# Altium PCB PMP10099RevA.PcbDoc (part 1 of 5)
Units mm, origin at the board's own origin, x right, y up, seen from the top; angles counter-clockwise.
Board outline 227.58 x 89.92 mm, 2 copper layers (Top Layer, Bottom Layer), stack 1.575 mm thick; 558 components, 261 nets, 1374 pads, 560 vias.
Unrouted connection lines stored in the file: 7.
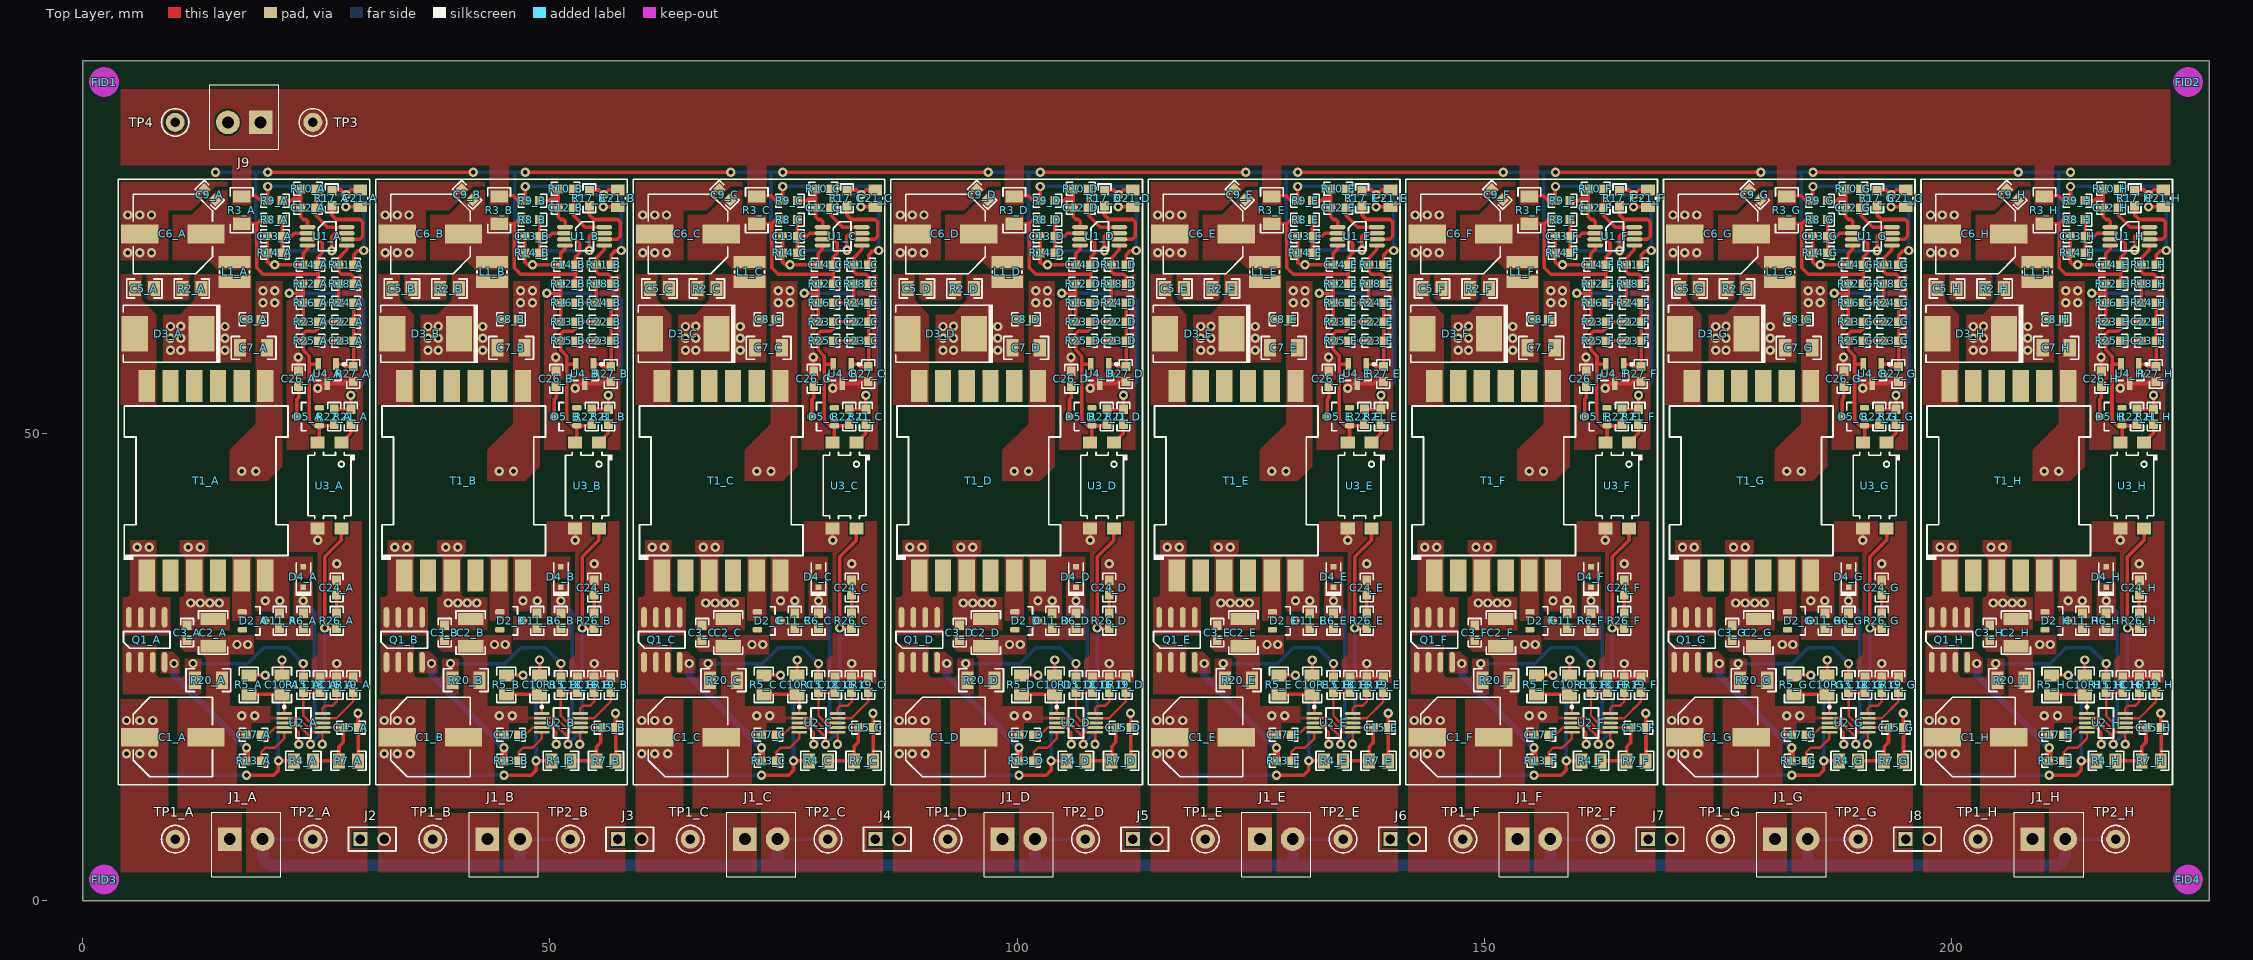
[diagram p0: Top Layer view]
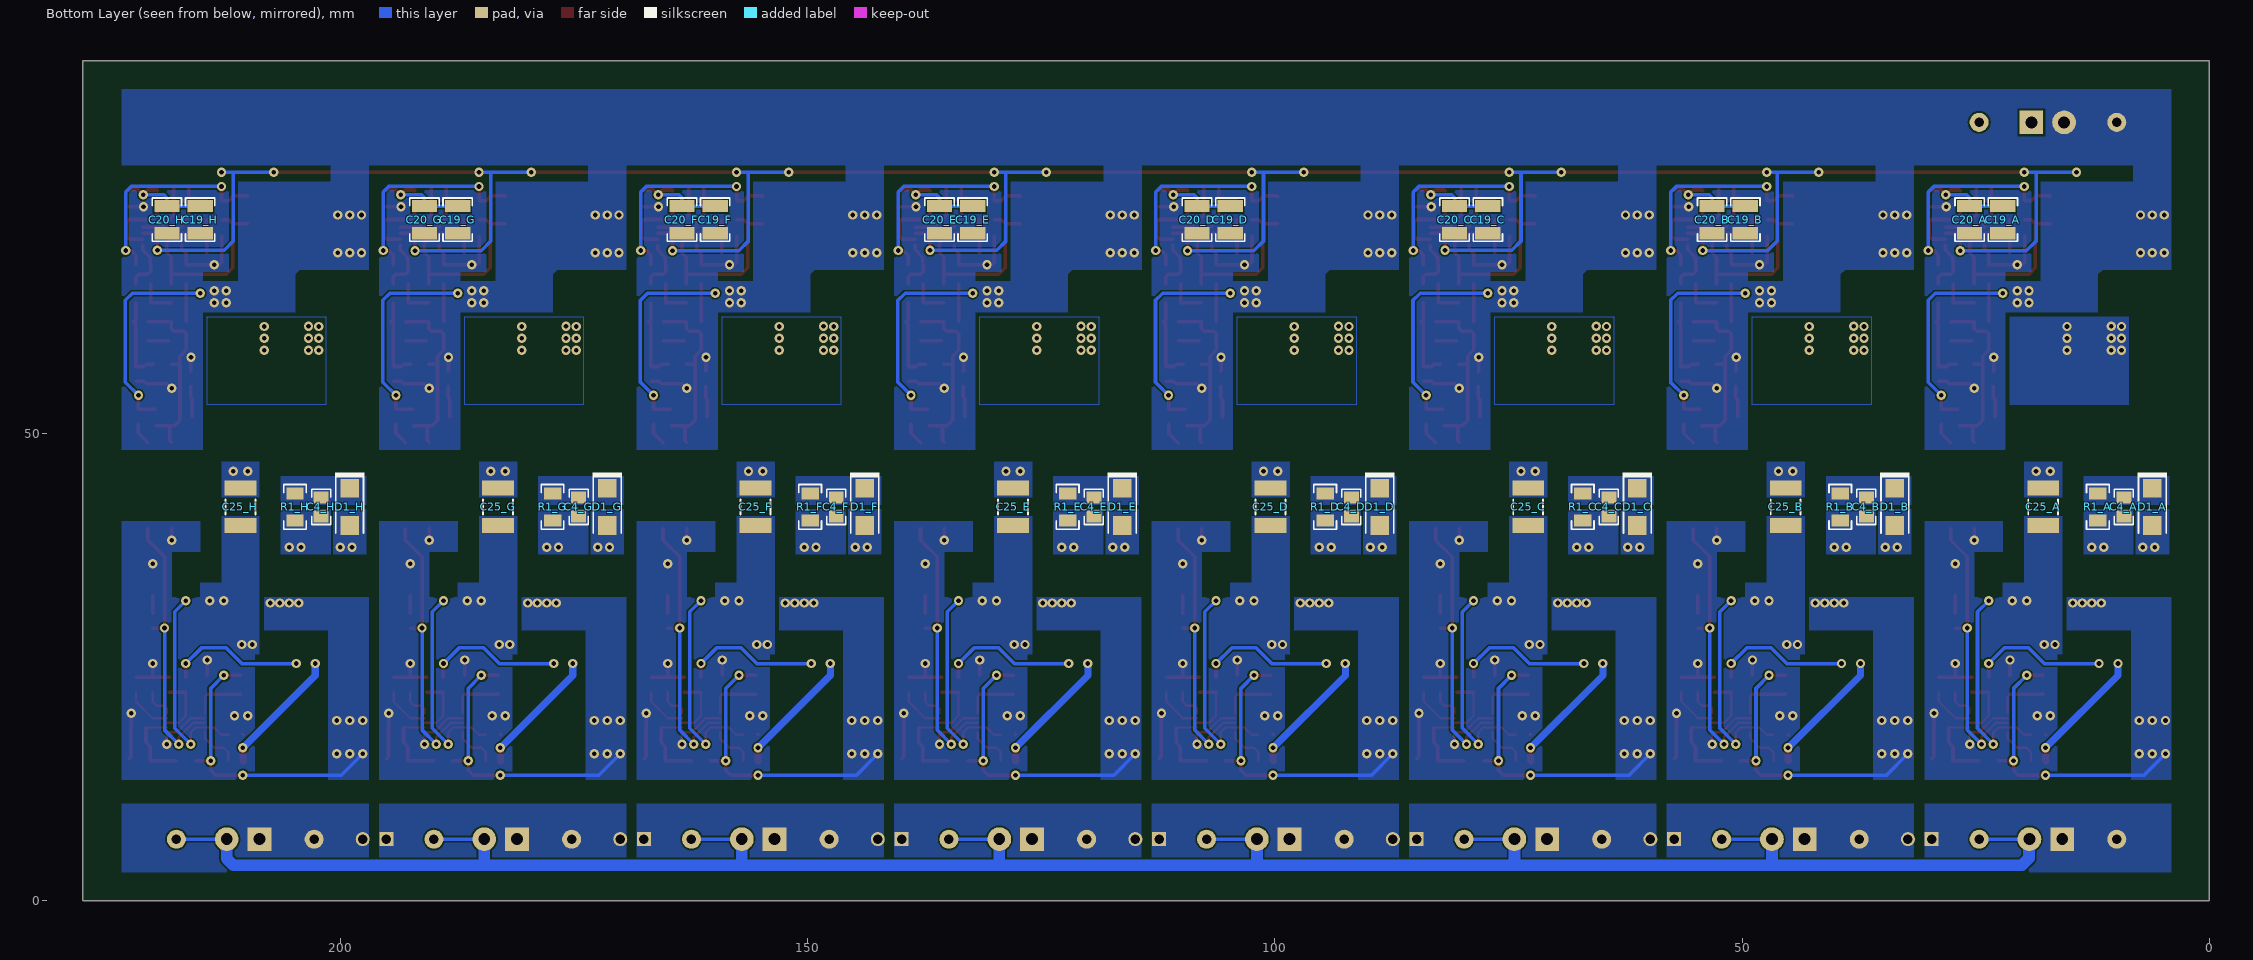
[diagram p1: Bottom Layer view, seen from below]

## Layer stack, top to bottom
Top Layer: signal copper 0.0356
Dielectric: core 1.5037, FR-4, Dk 4.8
Bottom Layer: signal copper 0.0356

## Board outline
0,0 227.584,0 227.584,89.916 0,89.916

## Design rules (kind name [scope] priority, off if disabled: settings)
Clearance [All] p1: gap=0.2
DiffPairsRouting [All] p1: maxlimit=10 minlimit=0.125 mostfreqgap=0.15 maxuncoupledlength=12.7
FabricationTestPointUsage FabricationTestPointUsage_1 [All] p1: valid=0 allowmultiple=FALSE
FabricationTestpoint FabricationTestpoint_1 [All] p1: side=3 testpointundercomponent=TRUE minsize=1.016 maxsize=2.54 preferedsize=1.524 minholesize=0 maxholesize=1.016 preferedholesize=0.813 testpointgrid=0.025 allowsidetop=TRUE allowsidebottom=TRUE usegrid=TRUE gridtolerance=0
Height [All] p1: minheight=0 maxheight=25.42 prefheight=12.7
HoleSize [All] p1: absolutevalues=TRUE maxlimit=6 minlimit=0.3 maxpercent=80.000 minpercent=20.000
HoleSize FabricationTestpoint [All] p2 off: absolutevalues=TRUE maxlimit=2.54 minlimit=0.025 maxpercent=80.000 minpercent=20.000
HoleSize FabricationTestPointUsage [All] p3 off: absolutevalues=TRUE maxlimit=2.54 minlimit=0.025 maxpercent=80.000 minpercent=20.000
MinimumAnnularRing [All] p1: minimumring=0.15
MinimumSolderMaskSliver [All] p1: minsoldermaskwidth=0.025
PlaneClearance [All] p1: clearance=0.5
PlaneConnect [All] p1: planeconnectstyle=Direct reliefexpansion=0.4 reliefentries=4 reliefconductorwidth=0.15 reliefairgap=0.15
PolygonConnect [All] p1: connectstyle=Direct reliefconductorwidth=0.15 reliefentries=4 polygonreliefangle="90 Angle" airgapwidth=0.254
RoomDefinition "PMP10099RevA - Top Level" [InComponentClass('PMP10099RevA - Top Level')] p1: confinementstyle=ConfineIn formatcopy=TRUE lockcomponents=FALSE outline 0,0 0,89.916 227.584,89.916 227.584,0
RoomDefinition H [InComponentClass('H')] p2: confinementstyle=ConfineIn formatcopy=TRUE lockcomponents=FALSE outline 196.723,2.54 223.647,2.54 223.647,77.216 196.723,77.216
RoomDefinition G [InComponentClass('G')] p3: confinementstyle=ConfineIn formatcopy=TRUE lockcomponents=FALSE outline 169.164,77.216 195.836,77.216 195.836,2.794 196.088,2.54 169.164,2.54
RoomDefinition F [InComponentClass('F')] p4: confinementstyle=ConfineIn formatcopy=TRUE lockcomponents=FALSE outline 141.605,2.54 168.529,2.54 168.529,77.216 141.605,77.216
RoomDefinition E [InComponentClass('E')] p5: confinementstyle=ConfineIn formatcopy=TRUE lockcomponents=FALSE outline 114.046,77.216 140.97,77.216 140.97,2.54 114.046,2.54
RoomDefinition D [InComponentClass('D')] p6: confinementstyle=ConfineIn formatcopy=TRUE lockcomponents=FALSE outline 86.487,2.54 113.411,2.54 113.411,77.216 86.487,77.216
RoomDefinition C [InComponentClass('C')] p7: confinementstyle=ConfineIn formatcopy=TRUE lockcomponents=FALSE outline 58.928,2.54 85.852,2.54 85.852,77.216 58.928,77.216
RoomDefinition B [InComponentClass('B')] p8: confinementstyle=ConfineIn formatcopy=TRUE lockcomponents=FALSE outline 31.369,2.54 31.369,77.216 58.293,77.216 58.293,2.54
RoomDefinition A [InComponentClass('A')] p9: confinementstyle=ConfineIn formatcopy=TRUE lockcomponents=FALSE outline 3.81,2.54 3.81,77.216 30.734,77.216 30.734,2.54
RoutingCorners [All] p1: cornerstyle=45-Degree minsetback=1.25 maxsetback=1.25
RoutingVias [All] p1: holewidth=0.3 width=0.7 viastyle="Through Hole" minholewidth=0.3 minwidth=0.5 maxholewidth=1 maxwidth=1.5
SilkToSilkClearance [All] p1: silktosilkclearance=0.1
SilkscreenOverComponentPads [All] p1: minsilkscreentomaskgap=0.127
SolderMaskExpansion [All] p1: expansion=0.075
Width [All] p1: maxlimit=10 minlimit=0.15 preferedwidth=0.254 minimp=50.000000 maximp=50.000000 favimp=50.000000
17 further rules are at their usual default settings.

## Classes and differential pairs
component class "PMP10099RevA - Top Level": FID1 FID2 FID3 FID4 J2 J3 J4 J5 J6 J7 J8 J9 TP3 TP4
component class A: C1_A C2_A C3_A C4_A C5_A C6_A C7_A C8_A C9_A C10_A C11_A C12_A C13_A C14_A C15_A C16_A C17_A C18_A C19_A C20_A C21_A C22_A C23_A C24_A C25_A C26_A D1_A D2_A D3_A D4_A D5_A J1_A L1_A Q1_A R1_A R2_A R3_A R4_A R5_A R6_A R7_A R8_A R9_A R10_A R11_A R12_A R13_A R14_A R15_A R16_A R17_A R18_A R19_A R20_A R21_A R22_A R23_A R24_A R25_A R26_A R27_A T1_A TP1_A TP2_A U1_A U2_A U3_A U4_A
component class Header: J2 J3 J4 J5 J6 J7 J8
component class B: C1_B C2_B C3_B C4_B C5_B C6_B C7_B C8_B C9_B C10_B C11_B C12_B C13_B C14_B C15_B C16_B C17_B C18_B C19_B C20_B C21_B C22_B C23_B C24_B C25_B C26_B D1_B D2_B D3_B D4_B D5_B J1_B L1_B Q1_B R1_B R2_B R3_B R4_B R5_B R6_B R7_B R8_B R9_B R10_B R11_B R12_B R13_B R14_B R15_B R16_B R17_B R18_B R19_B R20_B R21_B R22_B R23_B R24_B R25_B R26_B R27_B T1_B TP1_B TP2_B U1_B U2_B U3_B U4_B
component class C: C1_C C2_C C3_C C4_C C5_C C6_C C7_C C8_C C9_C C10_C C11_C C12_C C13_C C14_C C15_C C16_C C17_C C18_C C19_C C20_C C21_C C22_C C23_C C24_C C25_C C26_C D1_C D2_C D3_C D4_C D5_C J1_C L1_C Q1_C R1_C R2_C R3_C R4_C R5_C R6_C R7_C R8_C R9_C R10_C R11_C R12_C R13_C R14_C R15_C R16_C R17_C R18_C R19_C R20_C R21_C R22_C R23_C R24_C R25_C R26_C R27_C T1_C TP1_C TP2_C U1_C U2_C U3_C U4_C
component class D: C1_D C2_D C3_D C4_D C5_D C6_D C7_D C8_D C9_D C10_D C11_D C12_D C13_D C14_D C15_D C16_D C17_D C18_D C19_D C20_D C21_D C22_D C23_D C24_D C25_D C26_D D1_D D2_D D3_D D4_D D5_D J1_D L1_D Q1_D R1_D R2_D R3_D R4_D R5_D R6_D R7_D R8_D R9_D R10_D R11_D R12_D R13_D R14_D R15_D R16_D R17_D R18_D R19_D R20_D R21_D R22_D R23_D R24_D R25_D R26_D R27_D T1_D TP1_D TP2_D U1_D U2_D U3_D U4_D
component class E: C1_E C2_E C3_E C4_E C5_E C6_E C7_E C8_E C9_E C10_E C11_E C12_E C13_E C14_E C15_E C16_E C17_E C18_E C19_E C20_E C21_E C22_E C23_E C24_E C25_E C26_E D1_E D2_E D3_E D4_E D5_E J1_E L1_E Q1_E R1_E R2_E R3_E R4_E R5_E R6_E R7_E R8_E R9_E R10_E R11_E R12_E R13_E R14_E R15_E R16_E R17_E R18_E R19_E R20_E R21_E R22_E R23_E R24_E R25_E R26_E R27_E T1_E TP1_E TP2_E U1_E U2_E U3_E U4_E
component class F: C1_F C2_F C3_F C4_F C5_F C6_F C7_F C8_F C9_F C10_F C11_F C12_F C13_F C14_F C15_F C16_F C17_F C18_F C19_F C20_F C21_F C22_F C23_F C24_F C25_F C26_F D1_F D2_F D3_F D4_F D5_F J1_F L1_F Q1_F R1_F R2_F R3_F R4_F R5_F R6_F R7_F R8_F R9_F R10_F R11_F R12_F R13_F R14_F R15_F R16_F R17_F R18_F R19_F R20_F R21_F R22_F R23_F R24_F R25_F R26_F R27_F T1_F TP1_F TP2_F U1_F U2_F U3_F U4_F
component class G: C1_G C2_G C3_G C4_G C5_G C6_G C7_G C8_G C9_G C10_G C11_G C12_G C13_G C14_G C15_G C16_G C17_G C18_G C19_G C20_G C21_G C22_G C23_G C24_G C25_G C26_G D1_G D2_G D3_G D4_G D5_G J1_G L1_G Q1_G R1_G R2_G R3_G R4_G R5_G R6_G R7_G R8_G R9_G R10_G R11_G R12_G R13_G R14_G R15_G R16_G R17_G R18_G R19_G R20_G R21_G R22_G R23_G R24_G R25_G R26_G R27_G T1_G TP1_G TP2_G U1_G U2_G U3_G U4_G
component class H: C1_H C2_H C3_H C4_H C5_H C6_H C7_H C8_H C9_H C10_H C11_H C12_H C13_H C14_H C15_H C16_H C17_H C18_H C19_H C20_H C21_H C22_H C23_H C24_H C25_H C26_H D1_H D2_H D3_H D4_H D5_H J1_H L1_H Q1_H R1_H R2_H R3_H R4_H R5_H R6_H R7_H R8_H R9_H R10_H R11_H R12_H R13_H R14_H R15_H R16_H R17_H R18_H R19_H R20_H R21_H R22_H R23_H R24_H R25_H R26_H R27_H T1_H TP1_H TP2_H U1_H U2_H U3_H U4_H
channel class "PMP10099RevA - Circuit": A B C D E F G H
component class FiducialMark: FID1 FID2 FID3 FID4

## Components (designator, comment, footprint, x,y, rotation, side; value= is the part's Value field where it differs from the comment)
C1_A "EEE-FK1K220P" SM_RADIAL_F 9.652,17.526 r0 top (schematic designator C1)
C1_B "EEE-FK1K220P" SM_RADIAL_F 37.211,17.526 r0 top (schematic designator C1)
C1_C "EEE-FK1K220P" SM_RADIAL_F 64.77,17.526 r0 top (schematic designator C1)
C1_D "EEE-FK1K220P" SM_RADIAL_F 92.329,17.526 r0 top (schematic designator C1)
C1_E "EEE-FK1K220P" SM_RADIAL_F 119.888,17.526 r0 top (schematic designator C1)
C1_F "EEE-FK1K220P" SM_RADIAL_F 147.447,17.526 r0 top (schematic designator C1)
C1_G "EEE-FK1K220P" SM_RADIAL_F 175.006,17.526 r0 top (schematic designator C1)
C1_H "EEE-FK1K220P" SM_RADIAL_F 202.565,17.526 r0 top (schematic designator C1)
C2_A "GRM32ER72A225KA35L" 1210 13.97,28.702 r270 top (schematic designator C2)
C2_B "GRM32ER72A225KA35L" 1210 41.529,28.702 r270 top (schematic designator C2)
C2_C "GRM32ER72A225KA35L" 1210 69.088,28.702 r270 top (schematic designator C2)
C2_D "GRM32ER72A225KA35L" 1210 96.647,28.702 r270 top (schematic designator C2)
C2_E "GRM32ER72A225KA35L" 1210 124.206,28.702 r270 top (schematic designator C2)
C2_F "GRM32ER72A225KA35L" 1210 151.765,28.702 r270 top (schematic designator C2)
C2_G "GRM32ER72A225KA35L" 1210 179.324,28.702 r270 top (schematic designator C2)
C2_H "GRM32ER72A225KA35L" 1210 206.883,28.702 r270 top (schematic designator C2)
C3_A "GCM188R71H104KA57D" 0603 11.176,28.702 r270 top (schematic designator C3)
C3_B "GCM188R71H104KA57D" 0603 38.735,28.702 r270 top (schematic designator C3)
C3_C "GCM188R71H104KA57D" 0603 66.294,28.702 r270 top (schematic designator C3)
C3_D "GCM188R71H104KA57D" 0603 93.853,28.702 r270 top (schematic designator C3)
C3_E "GCM188R71H104KA57D" 0603 121.412,28.702 r270 top (schematic designator C3)
C3_F "GCM188R71H104KA57D" 0603 148.971,28.702 r270 top (schematic designator C3)
C3_G "GCM188R71H104KA57D" 0603 176.53,28.702 r270 top (schematic designator C3)
C3_H "GCM188R71H104KA57D" 0603 204.089,28.702 r270 top (schematic designator C3)
C4_A "HMK212B7104KG-T" 0805_HV 9.144,42.164 r90 bottom (schematic designator C4)
C4_B "HMK212B7104KG-T" 0805_HV 36.703,42.164 r90 bottom (schematic designator C4)
C4_C "HMK212B7104KG-T" 0805_HV 64.262,42.164 r90 bottom (schematic designator C4)
C4_D "HMK212B7104KG-T" 0805_HV 91.821,42.164 r90 bottom (schematic designator C4)
C4_E "HMK212B7104KG-T" 0805_HV 119.38,42.164 r90 bottom (schematic designator C4)
C4_F "HMK212B7104KG-T" 0805_HV 146.939,42.164 r90 bottom (schematic designator C4)
C4_G "HMK212B7104KG-T" 0805_HV 174.498,42.164 r90 bottom (schematic designator C4)
C4_H "HMK212B7104KG-T" 0805_HV 202.057,42.164 r90 bottom (schematic designator C4)
C5_A "GRM2195C2A330JZ01D" 0805_HV 6.604,65.532 r180 top (schematic designator C5)
C5_B "GRM2195C2A330JZ01D" 0805_HV 34.163,65.532 r180 top (schematic designator C5)
C5_C "GRM2195C2A330JZ01D" 0805_HV 61.722,65.532 r180 top (schematic designator C5)
C5_D "GRM2195C2A330JZ01D" 0805_HV 89.281,65.532 r180 top (schematic designator C5)
C5_E "GRM2195C2A330JZ01D" 0805_HV 116.84,65.532 r180 top (schematic designator C5)
C5_F "GRM2195C2A330JZ01D" 0805_HV 144.399,65.532 r180 top (schematic designator C5)
C5_G "GRM2195C2A330JZ01D" 0805_HV 171.958,65.532 r180 top (schematic designator C5)
C5_H "GRM2195C2A330JZ01D" 0805_HV 199.517,65.532 r180 top (schematic designator C5)
C6_A "EEE-FK1C331P" SM_RADIAL_F 9.652,71.374 r180 top (schematic designator C6)
C6_B "EEE-FK1C331P" SM_RADIAL_F 37.211,71.374 r180 top (schematic designator C6)
C6_C "EEE-FK1C331P" SM_RADIAL_F 64.77,71.374 r180 top (schematic designator C6)
C6_D "EEE-FK1C331P" SM_RADIAL_F 92.329,71.374 r180 top (schematic designator C6)
C6_E "EEE-FK1C331P" SM_RADIAL_F 119.888,71.374 r180 top (schematic designator C6)
C6_F "EEE-FK1C331P" SM_RADIAL_F 147.447,71.374 r180 top (schematic designator C6)
C6_G "EEE-FK1C331P" SM_RADIAL_F 175.006,71.374 r180 top (schematic designator C6)
C6_H "EEE-FK1C331P" SM_RADIAL_F 202.565,71.374 r180 top (schematic designator C6)
C7_A "GRM31CR71E106KA12L" 1206 18.288,59.182 r0 top (schematic designator C7)
C7_B "GRM31CR71E106KA12L" 1206 45.847,59.182 r0 top (schematic designator C7)
C7_C "GRM31CR71E106KA12L" 1206 73.406,59.182 r0 top (schematic designator C7)
C7_D "GRM31CR71E106KA12L" 1206 100.965,59.182 r0 top (schematic designator C7)
C7_E "GRM31CR71E106KA12L" 1206 128.524,59.182 r0 top (schematic designator C7)
C7_F "GRM31CR71E106KA12L" 1206 156.083,59.182 r0 top (schematic designator C7)
C7_G "GRM31CR71E106KA12L" 1206 183.642,59.182 r0 top (schematic designator C7)
C7_H "GRM31CR71E106KA12L" 1206 211.201,59.182 r0 top (schematic designator C7)
C8_A "GCM188R71H104KA57D" 0603 18.288,62.23 r0 top (schematic designator C8)
C8_B "GCM188R71H104KA57D" 0603 45.847,62.23 r0 top (schematic designator C8)
C8_C "GCM188R71H104KA57D" 0603 73.406,62.23 r0 top (schematic designator C8)
C8_D "GCM188R71H104KA57D" 0603 100.965,62.23 r0 top (schematic designator C8)
C8_E "GCM188R71H104KA57D" 0603 128.524,62.23 r0 top (schematic designator C8)
C8_F "GCM188R71H104KA57D" 0603 156.083,62.23 r0 top (schematic designator C8)
C8_G "GCM188R71H104KA57D" 0603 183.642,62.23 r0 top (schematic designator C8)
C8_H "GCM188R71H104KA57D" 0603 211.201,62.23 r0 top (schematic designator C8)
C9_A "GCM188R71H104KA57D" 0603 13.589,75.565 r135 top (schematic designator C9)
C9_B "GCM188R71H104KA57D" 0603 41.148,75.565 r135 top (schematic designator C9)
C9_C "GCM188R71H104KA57D" 0603 68.707,75.565 r135 top (schematic designator C9)
C9_D "GCM188R71H104KA57D" 0603 96.266,75.565 r135 top (schematic designator C9)
C9_E "GCM188R71H104KA57D" 0603 123.825,75.565 r135 top (schematic designator C9)
C9_F "GCM188R71H104KA57D" 0603 151.384,75.565 r135 top (schematic designator C9)
C9_G "GCM188R71H104KA57D" 0603 178.943,75.565 r135 top (schematic designator C9)
C9_H "GCM188R71H104KA57D" 0603 206.502,75.565 r135 top (schematic designator C9)
C10_A "HMK212B7104KG-T" 0805_HV 21.336,23.114 r90 top (schematic designator C10)
C10_B "HMK212B7104KG-T" 0805_HV 48.895,23.114 r90 top (schematic designator C10)
C10_C "HMK212B7104KG-T" 0805_HV 76.454,23.114 r90 top (schematic designator C10)
C10_D "HMK212B7104KG-T" 0805_HV 104.013,23.114 r90 top (schematic designator C10)
C10_E "HMK212B7104KG-T" 0805_HV 131.572,23.114 r90 top (schematic designator C10)
C10_F "HMK212B7104KG-T" 0805_HV 159.131,23.114 r90 top (schematic designator C10)
C10_G "HMK212B7104KG-T" 0805_HV 186.69,23.114 r90 top (schematic designator C10)
C10_H "HMK212B7104KG-T" 0805_HV 214.249,23.114 r90 top (schematic designator C10)
C11_A "GRM188R71E105KA12D" 0603 21.082,29.972 r90 top (schematic designator C11)
C11_B "GRM188R71E105KA12D" 0603 48.641,29.972 r90 top (schematic designator C11)
C11_C "GRM188R71E105KA12D" 0603 76.2,29.972 r90 top (schematic designator C11)
C11_D "GRM188R71E105KA12D" 0603 103.759,29.972 r90 top (schematic designator C11)
C11_E "GRM188R71E105KA12D" 0603 131.318,29.972 r90 top (schematic designator C11)
C11_F "GRM188R71E105KA12D" 0603 158.877,29.972 r90 top (schematic designator C11)
C11_G "GRM188R71E105KA12D" 0603 186.436,29.972 r90 top (schematic designator C11)
C11_H "GRM188R71E105KA12D" 0603 213.995,29.972 r90 top (schematic designator C11)
C12_A "GRM1885C1H560JA01D" 0603 24.13,74.168 r180 top (schematic designator C12)
C12_B "GRM1885C1H560JA01D" 0603 51.689,74.168 r180 top (schematic designator C12)
C12_C "GRM1885C1H560JA01D" 0603 79.248,74.168 r180 top (schematic designator C12)
C12_D "GRM1885C1H560JA01D" 0603 106.807,74.168 r180 top (schematic designator C12)
C12_E "GRM1885C1H560JA01D" 0603 134.366,74.168 r180 top (schematic designator C12)
C12_F "GRM1885C1H560JA01D" 0603 161.925,74.168 r180 top (schematic designator C12)
C12_G "GRM1885C1H560JA01D" 0603 189.484,74.168 r180 top (schematic designator C12)
C12_H "GRM1885C1H560JA01D" 0603 217.043,74.168 r180 top (schematic designator C12)
C13_A "GRM1885C1H560JA01D" 0603 20.574,71.12 r180 top (schematic designator C13)
C13_B "GRM1885C1H560JA01D" 0603 48.133,71.12 r180 top (schematic designator C13)
C13_C "GRM1885C1H560JA01D" 0603 75.692,71.12 r180 top (schematic designator C13)
C13_D "GRM1885C1H560JA01D" 0603 103.251,71.12 r180 top (schematic designator C13)
C13_E "GRM1885C1H560JA01D" 0603 130.81,71.12 r180 top (schematic designator C13)
C13_F "GRM1885C1H560JA01D" 0603 158.369,71.12 r180 top (schematic designator C13)
C13_G "GRM1885C1H560JA01D" 0603 185.928,71.12 r180 top (schematic designator C13)
C13_H "GRM1885C1H560JA01D" 0603 213.487,71.12 r180 top (schematic designator C13)
C14_A "GCM188R71H104KA57D" 0603 24.384,68.072 r180 top (schematic designator C14)
C14_B "GCM188R71H104KA57D" 0603 51.943,68.072 r180 top (schematic designator C14)
C14_C "GCM188R71H104KA57D" 0603 79.502,68.072 r180 top (schematic designator C14)
C14_D "GCM188R71H104KA57D" 0603 107.061,68.072 r180 top (schematic designator C14)
C14_E "GCM188R71H104KA57D" 0603 134.62,68.072 r180 top (schematic designator C14)
C14_F "GCM188R71H104KA57D" 0603 162.179,68.072 r180 top (schematic designator C14)
C14_G "GCM188R71H104KA57D" 0603 189.738,68.072 r180 top (schematic designator C14)
C14_H "GCM188R71H104KA57D" 0603 217.297,68.072 r180 top (schematic designator C14)
C15_A "GRM188R71H102KA01D" 0603 28.702,18.542 r0 top (schematic designator C15)
C15_B "GRM188R71H102KA01D" 0603 56.261,18.542 r0 top (schematic designator C15)
C15_C "GRM188R71H102KA01D" 0603 83.82,18.542 r0 top (schematic designator C15)
C15_D "GRM188R71H102KA01D" 0603 111.379,18.542 r0 top (schematic designator C15)
C15_E "GRM188R71H102KA01D" 0603 138.938,18.542 r0 top (schematic designator C15)
C15_F "GRM188R71H102KA01D" 0603 166.497,18.542 r0 top (schematic designator C15)
C15_G "GRM188R71H102KA01D" 0603 194.056,18.542 r0 top (schematic designator C15)
C15_H "GRM188R71H102KA01D" 0603 221.615,18.542 r0 top (schematic designator C15)
C16_A "GCM188R71H104KA57D" 0603 27.178,23.114 r90 top (schematic designator C16)
C16_B "GCM188R71H104KA57D" 0603 54.737,23.114 r90 top (schematic designator C16)
C16_C "GCM188R71H104KA57D" 0603 82.296,23.114 r90 top (schematic designator C16)
C16_D "GCM188R71H104KA57D" 0603 109.855,23.114 r90 top (schematic designator C16)
C16_E "GCM188R71H104KA57D" 0603 137.414,23.114 r90 top (schematic designator C16)
C16_F "GCM188R71H104KA57D" 0603 164.973,23.114 r90 top (schematic designator C16)
C16_G "GCM188R71H104KA57D" 0603 192.532,23.114 r90 top (schematic designator C16)
C16_H "GCM188R71H104KA57D" 0603 220.091,23.114 r90 top (schematic designator C16)
C17_A "GRM188R71E105KA12D" 0603 18.288,17.78 r180 top (schematic designator C17)
C17_B "GRM188R71E105KA12D" 0603 45.847,17.78 r180 top (schematic designator C17)
C17_C "GRM188R71E105KA12D" 0603 73.406,17.78 r180 top (schematic designator C17)
C17_D "GRM188R71E105KA12D" 0603 100.965,17.78 r180 top (schematic designator C17)
C17_E "GRM188R71E105KA12D" 0603 128.524,17.78 r180 top (schematic designator C17)
C17_F "GRM188R71E105KA12D" 0603 156.083,17.78 r180 top (schematic designator C17)
C17_G "GRM188R71E105KA12D" 0603 183.642,17.78 r180 top (schematic designator C17)
C17_H "GRM188R71E105KA12D" 0603 211.201,17.78 r180 top (schematic designator C17)
C18_A "GRM188R71H102KA01D" 0603 25.4,23.114 r90 top (schematic designator C18)
C18_B "GRM188R71H102KA01D" 0603 52.959,23.114 r90 top (schematic designator C18)
C18_C "GRM188R71H102KA01D" 0603 80.518,23.114 r90 top (schematic designator C18)
C18_D "GRM188R71H102KA01D" 0603 108.077,23.114 r90 top (schematic designator C18)
C18_E "GRM188R71H102KA01D" 0603 135.636,23.114 r90 top (schematic designator C18)
C18_F "GRM188R71H102KA01D" 0603 163.195,23.114 r90 top (schematic designator C18)
C18_G "GRM188R71H102KA01D" 0603 190.754,23.114 r90 top (schematic designator C18)
C18_H "GRM188R71H102KA01D" 0603 218.313,23.114 r90 top (schematic designator C18)
C19_A "GRM32ER70J476KE20L" 1210 22.098,72.898 r270 bottom (schematic designator C19)
C19_B "GRM32ER70J476KE20L" 1210 49.657,72.898 r270 bottom (schematic designator C19)
C19_C "GRM32ER70J476KE20L" 1210 77.216,72.898 r270 bottom (schematic designator C19)
C19_D "GRM32ER70J476KE20L" 1210 104.775,72.898 r270 bottom (schematic designator C19)
C19_E "GRM32ER70J476KE20L" 1210 132.334,72.898 r270 bottom (schematic designator C19)
C19_F "GRM32ER70J476KE20L" 1210 159.893,72.898 r270 bottom (schematic designator C19)
C19_G "GRM32ER70J476KE20L" 1210 187.452,72.898 r270 bottom (schematic designator C19)
C19_H "GRM32ER70J476KE20L" 1210 215.011,72.898 r270 bottom (schematic designator C19)
C20_A "GRM32ER70J476KE20L" 1210 25.654,72.898 r270 bottom (schematic designator C20)
C20_B "GRM32ER70J476KE20L" 1210 53.213,72.898 r270 bottom (schematic designator C20)
C20_C "GRM32ER70J476KE20L" 1210 80.772,72.898 r270 bottom (schematic designator C20)
C20_D "GRM32ER70J476KE20L" 1210 108.331,72.898 r270 bottom (schematic designator C20)
C20_E "GRM32ER70J476KE20L" 1210 135.89,72.898 r270 bottom (schematic designator C20)
C20_F "GRM32ER70J476KE20L" 1210 163.449,72.898 r270 bottom (schematic designator C20)
C20_G "GRM32ER70J476KE20L" 1210 191.008,72.898 r270 bottom (schematic designator C20)
C20_H "GRM32ER70J476KE20L" 1210 218.567,72.898 r270 bottom (schematic designator C20)
C21_A "GRM21BR71A106KE51K" 0805_140 29.718,75.184 r270 top (schematic designator C21)
C21_B "GRM21BR71A106KE51K" 0805_140 57.277,75.184 r270 top (schematic designator C21)
C21_C "GRM21BR71A106KE51K" 0805_140 84.836,75.184 r270 top (schematic designator C21)
C21_D "GRM21BR71A106KE51K" 0805_140 112.395,75.184 r270 top (schematic designator C21)
C21_E "GRM21BR71A106KE51K" 0805_140 139.954,75.184 r270 top (schematic designator C21)
C21_F "GRM21BR71A106KE51K" 0805_140 167.513,75.184 r270 top (schematic designator C21)
C21_G "GRM21BR71A106KE51K" 0805_140 195.072,75.184 r270 top (schematic designator C21)
C21_H "GRM21BR71A106KE51K" 0805_140 222.631,75.184 r270 top (schematic designator C21)
C22_A "GRM1885C1H220JA01D" 0603 28.194,61.976 r0 top (schematic designator C22)
C22_B "GRM1885C1H220JA01D" 0603 55.753,61.976 r0 top (schematic designator C22)
C22_C "GRM1885C1H220JA01D" 0603 83.312,61.976 r0 top (schematic designator C22)
C22_D "GRM1885C1H220JA01D" 0603 110.871,61.976 r0 top (schematic designator C22)
C22_E "GRM1885C1H220JA01D" 0603 138.43,61.976 r0 top (schematic designator C22)
C22_F "GRM1885C1H220JA01D" 0603 165.989,61.976 r0 top (schematic designator C22)
C22_G "GRM1885C1H220JA01D" 0603 193.548,61.976 r0 top (schematic designator C22)
C22_H "GRM1885C1H220JA01D" 0603 221.107,61.976 r0 top (schematic designator C22)
C23_A "GRM188R71H472KA01D" 0603 28.194,59.944 r0 top (schematic designator C23)
C23_B "GRM188R71H472KA01D" 0603 55.753,59.944 r0 top (schematic designator C23)
C23_C "GRM188R71H472KA01D" 0603 83.312,59.944 r0 top (schematic designator C23)
C23_D "GRM188R71H472KA01D" 0603 110.871,59.944 r0 top (schematic designator C23)
C23_E "GRM188R71H472KA01D" 0603 138.43,59.944 r0 top (schematic designator C23)
C23_F "GRM188R71H472KA01D" 0603 165.989,59.944 r0 top (schematic designator C23)
C23_G "GRM188R71H472KA01D" 0603 193.548,59.944 r0 top (schematic designator C23)
C23_H "GRM188R71H472KA01D" 0603 221.107,59.944 r0 top (schematic designator C23)
C24_A "GCM188R71H104KA57D" 0603 27.178,33.528 r90 top (schematic designator C24)
C24_B "GCM188R71H104KA57D" 0603 54.737,33.528 r90 top (schematic designator C24)
C24_C "GCM188R71H104KA57D" 0603 82.296,33.528 r90 top (schematic designator C24)
C24_D "GCM188R71H104KA57D" 0603 109.855,33.528 r90 top (schematic designator C24)
C24_E "GCM188R71H104KA57D" 0603 137.414,33.528 r90 top (schematic designator C24)
C24_F "GCM188R71H104KA57D" 0603 164.973,33.528 r90 top (schematic designator C24)
C24_G "GCM188R71H104KA57D" 0603 192.532,33.528 r90 top (schematic designator C24)
C24_H "GCM188R71H104KA57D" 0603 220.091,33.528 r90 top (schematic designator C24)
C25_A "1812GC102KA1" 1812 17.78,42.164 r270 bottom (schematic designator C25)
C25_B "1812GC102KA1" 1812 45.339,42.164 r270 bottom (schematic designator C25)
C25_C "1812GC102KA1" 1812 72.898,42.164 r270 bottom (schematic designator C25)
C25_D "1812GC102KA1" 1812 100.457,42.164 r270 bottom (schematic designator C25)
C25_E "1812GC102KA1" 1812 128.016,42.164 r270 bottom (schematic designator C25)
C25_F "1812GC102KA1" 1812 155.575,42.164 r270 bottom (schematic designator C25)
C25_G "1812GC102KA1" 1812 183.134,42.164 r270 bottom (schematic designator C25)
C25_H "1812GC102KA1" 1812 210.693,42.164 r270 bottom (schematic designator C25)
C26_A "GRM188R71E105KA12D" 0603 23.114,55.88 r90 top (schematic designator C26)
C26_B "GRM188R71E105KA12D" 0603 50.673,55.88 r90 top (schematic designator C26)
C26_C "GRM188R71E105KA12D" 0603 78.232,55.88 r90 top (schematic designator C26)
C26_D "GRM188R71E105KA12D" 0603 105.791,55.88 r90 top (schematic designator C26)
C26_E "GRM188R71E105KA12D" 0603 133.35,55.88 r90 top (schematic designator C26)
C26_F "GRM188R71E105KA12D" 0603 160.909,55.88 r90 top (schematic designator C26)
C26_G "GRM188R71E105KA12D" 0603 188.468,55.88 r90 top (schematic designator C26)
C26_H "GRM188R71E105KA12D" 0603 216.027,55.88 r90 top (schematic designator C26)
D1_A "MURA`10" SMA 6.096,42.164 r270 bottom (schematic designator D1)
D1_B "MURA`10" SMA 33.655,42.164 r270 bottom (schematic designator D1)
D1_C "MURA`10" SMA 61.214,42.164 r270 bottom (schematic designator D1)
D1_D "MURA`10" SMA 88.773,42.164 r270 bottom (schematic designator D1)
D1_E "MURA`10" SMA 116.332,42.164 r270 bottom (schematic designator D1)
D1_F "MURA`10" SMA 143.891,42.164 r270 bottom (schematic designator D1)
D1_G "MURA`10" SMA 171.45,42.164 r270 bottom (schematic designator D1)
D1_H "MURA`10" SMA 199.009,42.164 r270 bottom (schematic designator D1)
D2_A "BAS16" SOT-23 18.288,29.972 r0 top (schematic designator D2)
D2_B "BAS16" SOT-23 45.847,29.972 r0 top (schematic designator D2)
D2_C "BAS16" SOT-23 73.406,29.972 r0 top (schematic designator D2)
D2_D "BAS16" SOT-23 100.965,29.972 r0 top (schematic designator D2)
D2_E "BAS16" SOT-23 128.524,29.972 r0 top (schematic designator D2)
D2_F "BAS16" SOT-23 156.083,29.972 r0 top (schematic designator D2)
D2_G "BAS16" SOT-23 183.642,29.972 r0 top (schematic designator D2)
D2_H "BAS16" SOT-23 211.201,29.972 r0 top (schematic designator D2)
D3_A "MBRS360" SMC 9.144,60.706 r180 top (schematic designator D3)
D3_B "MBRS360" SMC 36.703,60.706 r180 top (schematic designator D3)
D3_C "MBRS360" SMC 64.262,60.706 r180 top (schematic designator D3)
D3_D "MBRS360" SMC 91.821,60.706 r180 top (schematic designator D3)
D3_E "MBRS360" SMC 119.38,60.706 r180 top (schematic designator D3)
D3_F "MBRS360" SMC 146.939,60.706 r180 top (schematic designator D3)
D3_G "MBRS360" SMC 174.498,60.706 r180 top (schematic designator D3)
D3_H "MBRS360" SMC 202.057,60.706 r180 top (schematic designator D3)
D4_A "BZX384-C12,115" sod-323 23.622,34.671 r90 top (schematic designator D4)
D4_B "BZX384-C12,115" sod-323 51.181,34.671 r90 top (schematic designator D4)
D4_C "BZX384-C12,115" sod-323 78.74,34.671 r90 top (schematic designator D4)
D4_D "BZX384-C12,115" sod-323 106.299,34.671 r90 top (schematic designator D4)
D4_E "BZX384-C12,115" sod-323 133.858,34.671 r90 top (schematic designator D4)
D4_F "BZX384-C12,115" sod-323 161.417,34.671 r90 top (schematic designator D4)
D4_G "BZX384-C12,115" sod-323 188.976,34.671 r90 top (schematic designator D4)
D4_H "BZX384-C12,115" sod-323 216.535,34.671 r90 top (schematic designator D4)
D5_A "BAS16" SOT-23 24.13,51.816 r180 top (schematic designator D5)
D5_B "BAS16" SOT-23 51.689,51.816 r180 top (schematic designator D5)
D5_C "BAS16" SOT-23 79.248,51.816 r180 top (schematic designator D5)
D5_D "BAS16" SOT-23 106.807,51.816 r180 top (schematic designator D5)
D5_E "BAS16" SOT-23 134.366,51.816 r180 top (schematic designator D5)
D5_F "BAS16" SOT-23 161.925,51.816 r180 top (schematic designator D5)
D5_G "BAS16" SOT-23 189.484,51.816 r180 top (schematic designator D5)
D5_H "BAS16" SOT-23 217.043,51.816 r180 top (schematic designator D5)
FID1 "Fiducial" Fiducial10-30 2.286,87.63 r0 top
FID2 "Fiducial" Fiducial10-30 225.298,87.63 r0 top
FID3 "Fiducial" Fiducial10-30 2.286,2.286 r0 top
FID4 "Fiducial" Fiducial10-30 225.298,2.286 r0 top
J1_A "ED555/2DS" TERM_BLK_ED555-2DS 15.748,6.604 r0 top (schematic designator J1)
J1_B "ED555/2DS" TERM_BLK_ED555-2DS 43.307,6.604 r0 top (schematic designator J1)
J1_C "ED555/2DS" TERM_BLK_ED555-2DS 70.866,6.604 r0 top (schematic designator J1)
J1_D "ED555/2DS" TERM_BLK_ED555-2DS 98.425,6.604 r0 top (schematic designator J1)
J1_E "ED555/2DS" TERM_BLK_ED555-2DS 125.984,6.604 r0 top (schematic designator J1)
J1_F "ED555/2DS" TERM_BLK_ED555-2DS 153.543,6.604 r0 top (schematic designator J1)
J1_G "ED555/2DS" TERM_BLK_ED555-2DS 181.102,6.604 r0 top (schematic designator J1)
J1_H "ED555/2DS" TERM_BLK_ED555-2DS 208.661,6.604 r0 top (schematic designator J1)
J2 "PEC02SAAN" CONN_PEC02SAAN 30.988,6.604 r0 top
J3 "PEC02SAAN" CONN_PEC02SAAN 58.547,6.604 r0 top
J4 "PEC02SAAN" CONN_PEC02SAAN 86.106,6.604 r0 top
J5 "PEC02SAAN" CONN_PEC02SAAN 113.665,6.604 r0 top
J6 "PEC02SAAN" CONN_PEC02SAAN 141.224,6.604 r0 top
J7 "PEC02SAAN" CONN_PEC02SAAN 168.783,6.604 r0 top
J8 "PEC02SAAN" CONN_PEC02SAAN 196.342,6.604 r0 top
J9 "ED555/2DS" TERM_BLK_ED555-2DS 19.05,83.312 r180 top
L1_A "330nH" WE-MAPI_3020 16.256,67.31 r90 top (schematic designator L1)
L1_B "330nH" WE-MAPI_3020 43.815,67.31 r90 top (schematic designator L1)
L1_C "330nH" WE-MAPI_3020 71.374,67.31 r90 top (schematic designator L1)
L1_D "330nH" WE-MAPI_3020 98.933,67.31 r90 top (schematic designator L1)
L1_E "330nH" WE-MAPI_3020 126.492,67.31 r90 top (schematic designator L1)
L1_F "330nH" WE-MAPI_3020 154.051,67.31 r90 top (schematic designator L1)
L1_G "330nH" WE-MAPI_3020 181.61,67.31 r90 top (schematic designator L1)
L1_H "330nH" WE-MAPI_3020 209.169,67.31 r90 top (schematic designator L1)
Q1_A "FDS86242" SOIC-8 6.858,27.94 r90 top (schematic designator Q1)
Q1_B "FDS86242" SOIC-8 34.417,27.94 r90 top (schematic designator Q1)
Q1_C "FDS86242" SOIC-8 61.976,27.94 r90 top (schematic designator Q1)
Q1_D "FDS86242" SOIC-8 89.535,27.94 r90 top (schematic designator Q1)
Q1_E "FDS86242" SOIC-8 117.094,27.94 r90 top (schematic designator Q1)
Q1_F "FDS86242" SOIC-8 144.653,27.94 r90 top (schematic designator Q1)
Q1_G "FDS86242" SOIC-8 172.212,27.94 r90 top (schematic designator Q1)
Q1_H "FDS86242" SOIC-8 199.771,27.94 r90 top (schematic designator Q1)
R1_A "CRCW120647K0JNEA" 1206 11.938,42.164 r270 bottom (schematic designator R1)
R1_B "CRCW120647K0JNEA" 1206 39.497,42.164 r270 bottom (schematic designator R1)
R1_C "CRCW120647K0JNEA" 1206 67.056,42.164 r270 bottom (schematic designator R1)
R1_D "CRCW120647K0JNEA" 1206 94.615,42.164 r270 bottom (schematic designator R1)
R1_E "CRCW120647K0JNEA" 1206 122.174,42.164 r270 bottom (schematic designator R1)
R1_F "CRCW120647K0JNEA" 1206 149.733,42.164 r270 bottom (schematic designator R1)
R1_G "CRCW120647K0JNEA" 1206 177.292,42.164 r270 bottom (schematic designator R1)
R1_H "CRCW120647K0JNEA" 1206 204.851,42.164 r270 bottom (schematic designator R1)
R2_A "CRCW0805100RJNEA" 0805_HV 11.684,65.532 r0 top (schematic designator R2)
R2_B "CRCW0805100RJNEA" 0805_HV 39.243,65.532 r0 top (schematic designator R2)
R2_C "CRCW0805100RJNEA" 0805_HV 66.802,65.532 r0 top (schematic designator R2)
R2_D "CRCW0805100RJNEA" 0805_HV 94.361,65.532 r0 top (schematic designator R2)
R2_E "CRCW0805100RJNEA" 0805_HV 121.92,65.532 r0 top (schematic designator R2)
R2_F "CRCW0805100RJNEA" 0805_HV 149.479,65.532 r0 top (schematic designator R2)
R2_G "CRCW0805100RJNEA" 0805_HV 177.038,65.532 r0 top (schematic designator R2)
R2_H "CRCW0805100RJNEA" 0805_HV 204.597,65.532 r0 top (schematic designator R2)
R3_A "ERJ-8RSJR10V" 1206 17.018,73.914 r90 top (schematic designator R3)
R3_B "ERJ-8RSJR10V" 1206 44.577,73.914 r90 top (schematic designator R3)
R3_C "ERJ-8RSJR10V" 1206 72.136,73.914 r90 top (schematic designator R3)
R3_D "ERJ-8RSJR10V" 1206 99.695,73.914 r90 top (schematic designator R3)
R3_E "ERJ-8RSJR10V" 1206 127.254,73.914 r90 top (schematic designator R3)
R3_F "ERJ-8RSJR10V" 1206 154.813,73.914 r90 top (schematic designator R3)
R3_G "ERJ-8RSJR10V" 1206 182.372,73.914 r90 top (schematic designator R3)
R3_H "ERJ-8RSJR10V" 1206 209.931,73.914 r90 top (schematic designator R3)
R4_A "CRCW080578K7FKEA" 0805_HV 23.622,14.986 r180 top (schematic designator R4)
R4_B "CRCW080578K7FKEA" 0805_HV 51.181,14.986 r180 top (schematic designator R4)
R4_C "CRCW080578K7FKEA" 0805_HV 78.74,14.986 r180 top (schematic designator R4)
R4_D "CRCW080578K7FKEA" 0805_HV 106.299,14.986 r180 top (schematic designator R4)
R4_E "CRCW080578K7FKEA" 0805_HV 133.858,14.986 r180 top (schematic designator R4)
R4_F "CRCW080578K7FKEA" 0805_HV 161.417,14.986 r180 top (schematic designator R4)
R4_G "CRCW080578K7FKEA" 0805_HV 188.976,14.986 r180 top (schematic designator R4)
R4_H "CRCW080578K7FKEA" 0805_HV 216.535,14.986 r180 top (schematic designator R4)
R5_A "CRCW080510R0FKEA" 0805_HV 17.78,23.114 r90 top (schematic designator R5)
R5_B "CRCW080510R0FKEA" 0805_HV 45.339,23.114 r90 top (schematic designator R5)
R5_C "CRCW080510R0FKEA" 0805_HV 72.898,23.114 r90 top (schematic designator R5)
R5_D "CRCW080510R0FKEA" 0805_HV 100.457,23.114 r90 top (schematic designator R5)
R5_E "CRCW080510R0FKEA" 0805_HV 128.016,23.114 r90 top (schematic designator R5)
R5_F "CRCW080510R0FKEA" 0805_HV 155.575,23.114 r90 top (schematic designator R5)
R5_G "CRCW080510R0FKEA" 0805_HV 183.134,23.114 r90 top (schematic designator R5)
R5_H "CRCW080510R0FKEA" 0805_HV 210.693,23.114 r90 top (schematic designator R5)
R6_A "CRCW060310R0FKEA" 0603 23.622,29.972 r270 top (schematic designator R6)
R6_B "CRCW060310R0FKEA" 0603 51.181,29.972 r270 top (schematic designator R6)
R6_C "CRCW060310R0FKEA" 0603 78.74,29.972 r270 top (schematic designator R6)
R6_D "CRCW060310R0FKEA" 0603 106.299,29.972 r270 top (schematic designator R6)
R6_E "CRCW060310R0FKEA" 0603 133.858,29.972 r270 top (schematic designator R6)
R6_F "CRCW060310R0FKEA" 0603 161.417,29.972 r270 top (schematic designator R6)
R6_G "CRCW060310R0FKEA" 0603 188.976,29.972 r270 top (schematic designator R6)
R6_H "CRCW060310R0FKEA" 0603 216.535,29.972 r270 top (schematic designator R6)
R7_A "CRCW08053K92FKEA" 0805_HV 28.448,14.986 r180 top (schematic designator R7)
R7_B "CRCW08053K92FKEA" 0805_HV 56.007,14.986 r180 top (schematic designator R7)
R7_C "CRCW08053K92FKEA" 0805_HV 83.566,14.986 r180 top (schematic designator R7)
R7_D "CRCW08053K92FKEA" 0805_HV 111.125,14.986 r180 top (schematic designator R7)
R7_E "CRCW08053K92FKEA" 0805_HV 138.684,14.986 r180 top (schematic designator R7)
R7_F "CRCW08053K92FKEA" 0805_HV 166.243,14.986 r180 top (schematic designator R7)
R7_G "CRCW08053K92FKEA" 0805_HV 193.802,14.986 r180 top (schematic designator R7)
R7_H "CRCW08053K92FKEA" 0805_HV 221.361,14.986 r180 top (schematic designator R7)
R8_A "CRCW0603499RFKEA" 0603 20.574,72.898 r180 top (schematic designator R8)
R8_B "CRCW0603499RFKEA" 0603 48.133,72.898 r180 top (schematic designator R8)
R8_C "CRCW0603499RFKEA" 0603 75.692,72.898 r180 top (schematic designator R8)
R8_D "CRCW0603499RFKEA" 0603 103.251,72.898 r180 top (schematic designator R8)
R8_E "CRCW0603499RFKEA" 0603 130.81,72.898 r180 top (schematic designator R8)
R8_F "CRCW0603499RFKEA" 0603 158.369,72.898 r180 top (schematic designator R8)
R8_G "CRCW0603499RFKEA" 0603 185.928,72.898 r180 top (schematic designator R8)
R8_H "CRCW0603499RFKEA" 0603 213.487,72.898 r180 top (schematic designator R8)
R9_A "CRCW0603499RFKEA" 0603 20.574,74.93 r180 top (schematic designator R9)
R9_B "CRCW0603499RFKEA" 0603 48.133,74.93 r180 top (schematic designator R9)
R9_C "CRCW0603499RFKEA" 0603 75.692,74.93 r180 top (schematic designator R9)
R9_D "CRCW0603499RFKEA" 0603 103.251,74.93 r180 top (schematic designator R9)
R9_E "CRCW0603499RFKEA" 0603 130.81,74.93 r180 top (schematic designator R9)
R9_F "CRCW0603499RFKEA" 0603 158.369,74.93 r180 top (schematic designator R9)
R9_G "CRCW0603499RFKEA" 0603 185.928,74.93 r180 top (schematic designator R9)
R9_H "CRCW0603499RFKEA" 0603 213.487,74.93 r180 top (schematic designator R9)
R10_A "CRCW060345K3FKEA" 0603 24.13,76.2 r0 top (schematic designator R10)
R10_B "CRCW060345K3FKEA" 0603 51.689,76.2 r0 top (schematic designator R10)
R10_C "CRCW060345K3FKEA" 0603 79.248,76.2 r0 top (schematic designator R10)
R10_D "CRCW060345K3FKEA" 0603 106.807,76.2 r0 top (schematic designator R10)
R10_E "CRCW060345K3FKEA" 0603 134.366,76.2 r0 top (schematic designator R10)
R10_F "CRCW060345K3FKEA" 0603 161.925,76.2 r0 top (schematic designator R10)
R10_G "CRCW060345K3FKEA" 0603 189.484,76.2 r0 top (schematic designator R10)
R10_H "CRCW060345K3FKEA" 0603 217.043,76.2 r0 top (schematic designator R10)
R11_A "CRCW0603200RFKEA" 0603 28.194,68.072 r0 top (schematic designator R11)
R11_B "CRCW0603200RFKEA" 0603 55.753,68.072 r0 top (schematic designator R11)
R11_C "CRCW0603200RFKEA" 0603 83.312,68.072 r0 top (schematic designator R11)
R11_D "CRCW0603200RFKEA" 0603 110.871,68.072 r0 top (schematic designator R11)
R11_E "CRCW0603200RFKEA" 0603 138.43,68.072 r0 top (schematic designator R11)
R11_F "CRCW0603200RFKEA" 0603 165.989,68.072 r0 top (schematic designator R11)
R11_G "CRCW0603200RFKEA" 0603 193.548,68.072 r0 top (schematic designator R11)
R11_H "CRCW0603200RFKEA" 0603 221.107,68.072 r0 top (schematic designator R11)
R12_A "CRCW06030000Z0EA" 0603 24.384,66.04 r0 top (schematic designator R12)
R12_B "CRCW06030000Z0EA" 0603 51.943,66.04 r0 top (schematic designator R12)
R12_C "CRCW06030000Z0EA" 0603 79.502,66.04 r0 top (schematic designator R12)
R12_D "CRCW06030000Z0EA" 0603 107.061,66.04 r0 top (schematic designator R12)
R12_E "CRCW06030000Z0EA" 0603 134.62,66.04 r0 top (schematic designator R12)
R12_F "CRCW06030000Z0EA" 0603 162.179,66.04 r0 top (schematic designator R12)
R12_G "CRCW06030000Z0EA" 0603 189.738,66.04 r0 top (schematic designator R12)
R12_H "CRCW06030000Z0EA" 0603 217.297,66.04 r0 top (schematic designator R12)
R13_A "CRCW06030000Z0EA" 0603 18.288,14.986 r180 top (schematic designator R13)
R13_B "CRCW06030000Z0EA" 0603 45.847,14.986 r180 top (schematic designator R13)
R13_C "CRCW06030000Z0EA" 0603 73.406,14.986 r180 top (schematic designator R13)
R13_D "CRCW06030000Z0EA" 0603 100.965,14.986 r180 top (schematic designator R13)
R13_E "CRCW06030000Z0EA" 0603 128.524,14.986 r180 top (schematic designator R13)
R13_F "CRCW06030000Z0EA" 0603 156.083,14.986 r180 top (schematic designator R13)
R13_G "CRCW06030000Z0EA" 0603 183.642,14.986 r180 top (schematic designator R13)
R13_H "CRCW06030000Z0EA" 0603 211.201,14.986 r180 top (schematic designator R13)
R14_A "CRCW060345K3FKEA" 0603 20.574,69.342 r0 top (schematic designator R14)
R14_B "CRCW060345K3FKEA" 0603 48.133,69.342 r0 top (schematic designator R14)
R14_C "CRCW060345K3FKEA" 0603 75.692,69.342 r0 top (schematic designator R14)
R14_D "CRCW060345K3FKEA" 0603 103.251,69.342 r0 top (schematic designator R14)
R14_E "CRCW060345K3FKEA" 0603 130.81,69.342 r0 top (schematic designator R14)
R14_F "CRCW060345K3FKEA" 0603 158.369,69.342 r0 top (schematic designator R14)
R14_G "CRCW060345K3FKEA" 0603 185.928,69.342 r0 top (schematic designator R14)
R14_H "CRCW060345K3FKEA" 0603 213.487,69.342 r0 top (schematic designator R14)
R15_A "CRCW0603100RFKEA" 0603 23.622,23.114 r90 top (schematic designator R15)
R15_B "CRCW0603100RFKEA" 0603 51.181,23.114 r90 top (schematic designator R15)
R15_C "CRCW0603100RFKEA" 0603 78.74,23.114 r90 top (schematic designator R15)
R15_D "CRCW0603100RFKEA" 0603 106.299,23.114 r90 top (schematic designator R15)
R15_E "CRCW0603100RFKEA" 0603 133.858,23.114 r90 top (schematic designator R15)
R15_F "CRCW0603100RFKEA" 0603 161.417,23.114 r90 top (schematic designator R15)
R15_G "CRCW0603100RFKEA" 0603 188.976,23.114 r90 top (schematic designator R15)
R15_H "CRCW0603100RFKEA" 0603 216.535,23.114 r90 top (schematic designator R15)
R16_A "CRCW0603154RFKEA" 0603 24.384,64.008 r0 top (schematic designator R16)
R16_B "CRCW0603154RFKEA" 0603 51.943,64.008 r0 top (schematic designator R16)
R16_C "CRCW0603154RFKEA" 0603 79.502,64.008 r0 top (schematic designator R16)
R16_D "CRCW0603154RFKEA" 0603 107.061,64.008 r0 top (schematic designator R16)
R16_E "CRCW0603154RFKEA" 0603 134.62,64.008 r0 top (schematic designator R16)
R16_F "CRCW0603154RFKEA" 0603 162.179,64.008 r0 top (schematic designator R16)
R16_G "CRCW0603154RFKEA" 0603 189.738,64.008 r0 top (schematic designator R16)
R16_H "CRCW0603154RFKEA" 0603 217.297,64.008 r0 top (schematic designator R16)
R17_A "CRCW06033R32FKEA" 0603 26.67,75.184 r270 top (schematic designator R17)
R17_B "CRCW06033R32FKEA" 0603 54.229,75.184 r270 top (schematic designator R17)
R17_C "CRCW06033R32FKEA" 0603 81.788,75.184 r270 top (schematic designator R17)
R17_D "CRCW06033R32FKEA" 0603 109.347,75.184 r270 top (schematic designator R17)
R17_E "CRCW06033R32FKEA" 0603 136.906,75.184 r270 top (schematic designator R17)
R17_F "CRCW06033R32FKEA" 0603 164.465,75.184 r270 top (schematic designator R17)
R17_G "CRCW06033R32FKEA" 0603 192.024,75.184 r270 top (schematic designator R17)
R17_H "CRCW06033R32FKEA" 0603 219.583,75.184 r270 top (schematic designator R17)
R18_A "CRCW06030000Z0EA" 0603 28.194,66.04 r0 top (schematic designator R18)
R18_B "CRCW06030000Z0EA" 0603 55.753,66.04 r0 top (schematic designator R18)
R18_C "CRCW06030000Z0EA" 0603 83.312,66.04 r0 top (schematic designator R18)
R18_D "CRCW06030000Z0EA" 0603 110.871,66.04 r0 top (schematic designator R18)
R18_E "CRCW06030000Z0EA" 0603 138.43,66.04 r0 top (schematic designator R18)
R18_F "CRCW06030000Z0EA" 0603 165.989,66.04 r0 top (schematic designator R18)
R18_G "CRCW06030000Z0EA" 0603 193.548,66.04 r0 top (schematic designator R18)
R18_H "CRCW06030000Z0EA" 0603 221.107,66.04 r0 top (schematic designator R18)
R19_A "CRCW060348K7FKEA" 0603 28.956,23.114 r270 top (schematic designator R19)
R19_B "CRCW060348K7FKEA" 0603 56.515,23.114 r270 top (schematic designator R19)
R19_C "CRCW060348K7FKEA" 0603 84.074,23.114 r270 top (schematic designator R19)
R19_D "CRCW060348K7FKEA" 0603 111.633,23.114 r270 top (schematic designator R19)
R19_E "CRCW060348K7FKEA" 0603 139.192,23.114 r270 top (schematic designator R19)
R19_F "CRCW060348K7FKEA" 0603 166.751,23.114 r270 top (schematic designator R19)
R19_G "CRCW060348K7FKEA" 0603 194.31,23.114 r270 top (schematic designator R19)
R19_H "CRCW060348K7FKEA" 0603 221.869,23.114 r270 top (schematic designator R19)
R20_A "ERJ-8RQFR27V" 1206 13.462,23.622 r180 top (schematic designator R20)
R20_B "ERJ-8RQFR27V" 1206 41.021,23.622 r180 top (schematic designator R20)
R20_C "ERJ-8RQFR27V" 1206 68.58,23.622 r180 top (schematic designator R20)
R20_D "ERJ-8RQFR27V" 1206 96.139,23.622 r180 top (schematic designator R20)
R20_E "ERJ-8RQFR27V" 1206 123.698,23.622 r180 top (schematic designator R20)
R20_F "ERJ-8RQFR27V" 1206 151.257,23.622 r180 top (schematic designator R20)
R20_G "ERJ-8RQFR27V" 1206 178.816,23.622 r180 top (schematic designator R20)
R20_H "ERJ-8RQFR27V" 1206 206.375,23.622 r180 top (schematic designator R20)
R21_A "CRCW06032K49FKEA" 0603 28.702,51.816 r90 top (schematic designator R21)
R21_B "CRCW06032K49FKEA" 0603 56.261,51.816 r90 top (schematic designator R21)
R21_C "CRCW06032K49FKEA" 0603 83.82,51.816 r90 top (schematic designator R21)
R21_D "CRCW06032K49FKEA" 0603 111.379,51.816 r90 top (schematic designator R21)
R21_E "CRCW06032K49FKEA" 0603 138.938,51.816 r90 top (schematic designator R21)
R21_F "CRCW06032K49FKEA" 0603 166.497,51.816 r90 top (schematic designator R21)
R21_G "CRCW06032K49FKEA" 0603 194.056,51.816 r90 top (schematic designator R21)
R21_H "CRCW06032K49FKEA" 0603 221.615,51.816 r90 top (schematic designator R21)
R22_A "CRCW060310K0FKEA" 0603 26.924,51.816 r270 top (schematic designator R22)
R22_B "CRCW060310K0FKEA" 0603 54.483,51.816 r270 top (schematic designator R22)
R22_C "CRCW060310K0FKEA" 0603 82.042,51.816 r270 top (schematic designator R22)
R22_D "CRCW060310K0FKEA" 0603 109.601,51.816 r270 top (schematic designator R22)
R22_E "CRCW060310K0FKEA" 0603 137.16,51.816 r270 top (schematic designator R22)
R22_F "CRCW060310K0FKEA" 0603 164.719,51.816 r270 top (schematic designator R22)
R22_G "CRCW060310K0FKEA" 0603 192.278,51.816 r270 top (schematic designator R22)
R22_H "CRCW060310K0FKEA" 0603 219.837,51.816 r270 top (schematic designator R22)
R23_A "CRCW06032K49FKEA" 0603 24.384,61.976 r180 top (schematic designator R23)
R23_B "CRCW06032K49FKEA" 0603 51.943,61.976 r180 top (schematic designator R23)
R23_C "CRCW06032K49FKEA" 0603 79.502,61.976 r180 top (schematic designator R23)
R23_D "CRCW06032K49FKEA" 0603 107.061,61.976 r180 top (schematic designator R23)
R23_E "CRCW06032K49FKEA" 0603 134.62,61.976 r180 top (schematic designator R23)
R23_F "CRCW06032K49FKEA" 0603 162.179,61.976 r180 top (schematic designator R23)
R23_G "CRCW06032K49FKEA" 0603 189.738,61.976 r180 top (schematic designator R23)
R23_H "CRCW06032K49FKEA" 0603 217.297,61.976 r180 top (schematic designator R23)
R24_A "CRCW0603100KFKEA" 0603 28.194,64.008 r180 top (schematic designator R24)
R24_B "CRCW0603100KFKEA" 0603 55.753,64.008 r180 top (schematic designator R24)
R24_C "CRCW0603100KFKEA" 0603 83.312,64.008 r180 top (schematic designator R24)
R24_D "CRCW0603100KFKEA" 0603 110.871,64.008 r180 top (schematic designator R24)
R24_E "CRCW0603100KFKEA" 0603 138.43,64.008 r180 top (schematic designator R24)
R24_F "CRCW0603100KFKEA" 0603 165.989,64.008 r180 top (schematic designator R24)
R24_G "CRCW0603100KFKEA" 0603 193.548,64.008 r180 top (schematic designator R24)
R24_H "CRCW0603100KFKEA" 0603 221.107,64.008 r180 top (schematic designator R24)
R25_A "CRCW0603100KFKEA" 0603 24.384,59.944 r180 top (schematic designator R25)
R25_B "CRCW0603100KFKEA" 0603 51.943,59.944 r180 top (schematic designator R25)
R25_C "CRCW0603100KFKEA" 0603 79.502,59.944 r180 top (schematic designator R25)
R25_D "CRCW0603100KFKEA" 0603 107.061,59.944 r180 top (schematic designator R25)
R25_E "CRCW0603100KFKEA" 0603 134.62,59.944 r180 top (schematic designator R25)
R25_F "CRCW0603100KFKEA" 0603 162.179,59.944 r180 top (schematic designator R25)
R25_G "CRCW0603100KFKEA" 0603 189.738,59.944 r180 top (schematic designator R25)
R25_H "CRCW0603100KFKEA" 0603 217.297,59.944 r180 top (schematic designator R25)
R26_A "CRCW06031K00FKEA" 0603 27.178,29.972 r270 top (schematic designator R26)
R26_B "CRCW06031K00FKEA" 0603 54.737,29.972 r270 top (schematic designator R26)
R26_C "CRCW06031K00FKEA" 0603 82.296,29.972 r270 top (schematic designator R26)
R26_D "CRCW06031K00FKEA" 0603 109.855,29.972 r270 top (schematic designator R26)
R26_E "CRCW06031K00FKEA" 0603 137.414,29.972 r270 top (schematic designator R26)
R26_F "CRCW06031K00FKEA" 0603 164.973,29.972 r270 top (schematic designator R26)
R26_G "CRCW06031K00FKEA" 0603 192.532,29.972 r270 top (schematic designator R26)
R26_H "CRCW06031K00FKEA" 0603 220.091,29.972 r270 top (schematic designator R26)
R27_A "CRCW060311K5FKEA" 0603 28.956,56.388 r90 top (schematic designator R27)
R27_B "CRCW060311K5FKEA" 0603 56.515,56.388 r90 top (schematic designator R27)
R27_C "CRCW060311K5FKEA" 0603 84.074,56.388 r90 top (schematic designator R27)
R27_D "CRCW060311K5FKEA" 0603 111.633,56.388 r90 top (schematic designator R27)
R27_E "CRCW060311K5FKEA" 0603 139.192,56.388 r90 top (schematic designator R27)
R27_F "CRCW060311K5FKEA" 0603 166.751,56.388 r90 top (schematic designator R27)
R27_G "CRCW060311K5FKEA" 0603 194.31,56.388 r90 top (schematic designator R27)
R27_H "CRCW060311K5FKEA" 0603 221.869,56.388 r90 top (schematic designator R27)
T1_A "7491193912" WURTH_7491193912 13.208,44.958 r90 top (schematic designator T1)
T1_B "7491193912" WURTH_7491193912 40.767,44.958 r90 top (schematic designator T1)
T1_C "7491193912" WURTH_7491193912 68.326,44.958 r90 top (schematic designator T1)
T1_D "7491193912" WURTH_7491193912 95.885,44.958 r90 top (schematic designator T1)
T1_E "7491193912" WURTH_7491193912 123.444,44.958 r90 top (schematic designator T1)
T1_F "7491193912" WURTH_7491193912 151.003,44.958 r90 top (schematic designator T1)
T1_G "7491193912" WURTH_7491193912 178.562,44.958 r90 top (schematic designator T1)
T1_H "7491193912" WURTH_7491193912 206.121,44.958 r90 top (schematic designator T1)
TP1_A "5000" Keystone5000 9.906,6.604 r90 top (schematic designator TP1)
TP1_B "5000" Keystone5000 37.465,6.604 r90 top (schematic designator TP1)
TP1_C "5000" Keystone5000 65.024,6.604 r90 top (schematic designator TP1)
TP1_D "5000" Keystone5000 92.583,6.604 r90 top (schematic designator TP1)
TP1_E "5000" Keystone5000 120.142,6.604 r90 top (schematic designator TP1)
TP1_F "5000" Keystone5000 147.701,6.604 r90 top (schematic designator TP1)
TP1_G "5000" Keystone5000 175.26,6.604 r90 top (schematic designator TP1)
TP1_H "5000" Keystone5000 202.819,6.604 r90 top (schematic designator TP1)
TP2_A "5001" Keystone5001 24.638,6.604 r90 top (schematic designator TP2)
TP2_B "5001" Keystone5001 52.197,6.604 r90 top (schematic designator TP2)
TP2_C "5001" Keystone5001 79.756,6.604 r90 top (schematic designator TP2)
TP2_D "5001" Keystone5001 107.315,6.604 r90 top (schematic designator TP2)
TP2_E "5001" Keystone5001 134.874,6.604 r90 top (schematic designator TP2)
TP2_F "5001" Keystone5001 162.433,6.604 r90 top (schematic designator TP2)
TP2_G "5001" Keystone5001 189.992,6.604 r90 top (schematic designator TP2)
TP2_H "5001" Keystone5001 217.551,6.604 r90 top (schematic designator TP2)
TP3 "5000" Keystone5000 24.638,83.312 r90 top
TP4 "5001" Keystone5001 9.906,83.312 r90 top
U1_A "UCC29002" DGK0008A_N 26.162,71.12 r0 top (schematic designator U1)
U1_B "UCC29002" DGK0008A_N 53.721,71.12 r0 top (schematic designator U1)
U1_C "UCC29002" DGK0008A_N 81.28,71.12 r0 top (schematic designator U1)
U1_D "UCC29002" DGK0008A_N 108.839,71.12 r0 top (schematic designator U1)
U1_E "UCC29002" DGK0008A_N 136.398,71.12 r0 top (schematic designator U1)
U1_F "UCC29002" DGK0008A_N 163.957,71.12 r0 top (schematic designator U1)
U1_G "UCC29002" DGK0008A_N 191.516,71.12 r0 top (schematic designator U1)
